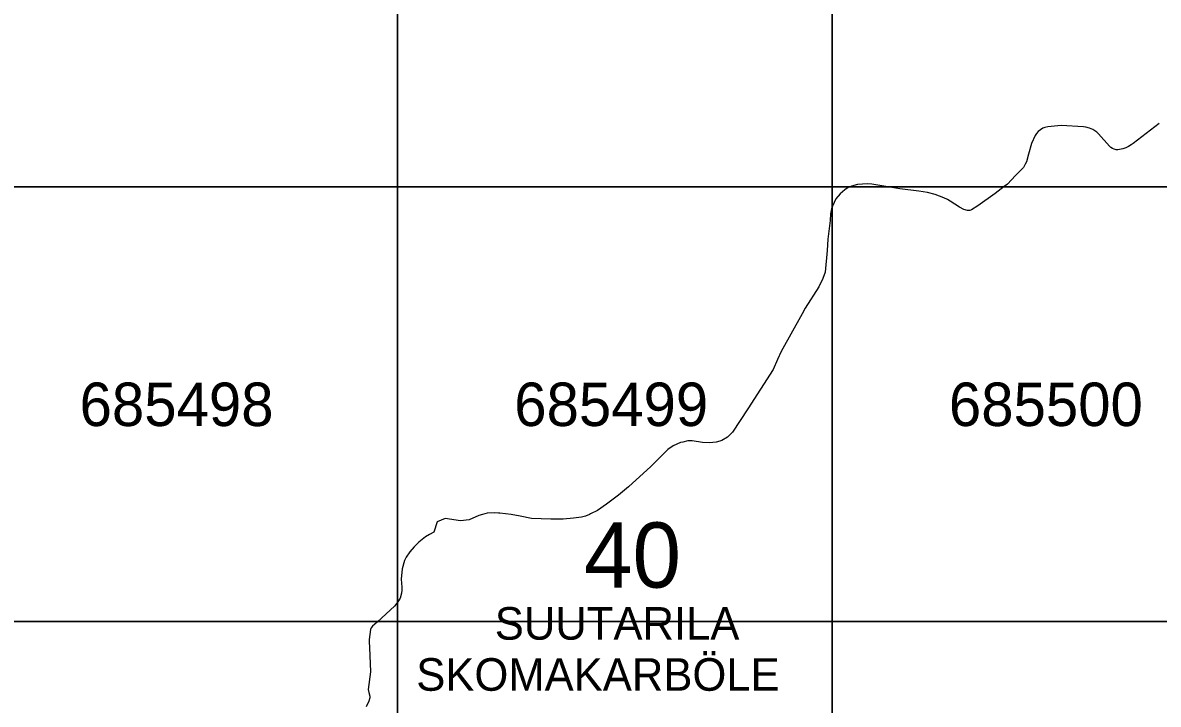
# Model space of a CAD drawing. Extents: x 25485000 to 25520000, y 6656775 to 6690000.
# Drawn here: x 25498138 to 25500750, y 6684810 to 6686378 of the extents above; entities that cross this region are included whole.
import ezdxf

# ---------------------------------------------------------------- set-up
doc = ezdxf.new("R2010")
doc.units = 0
doc.layers.add('Level 63', color=7, linetype='Continuous')

msp = doc.modelspace()

# ---------------------------------------------------------------- linework, layer by layer
at = {"layer": 'Level 63'}
for points in [[(25498000, 6686000), (25499000, 6686000), (25499000, 6687000), (25498000, 6687000)], [(25499000, 6686000), (25500000, 6686000), (25500000, 6687000), (25499000, 6687000)], [(25500000, 6686000), (25501000, 6686000), (25501000, 6687000), (25500000, 6687000)], [(25498000, 6685000), (25499000, 6685000), (25499000, 6686000), (25498000, 6686000)], [(25499000, 6685000), (25500000, 6685000), (25500000, 6686000), (25499000, 6686000)], [(25500000, 6685000), (25501000, 6685000), (25501000, 6686000), (25500000, 6686000)], [(25498000, 6684000), (25499000, 6684000), (25499000, 6685000), (25498000, 6685000)], [(25499000, 6684000), (25500000, 6684000), (25500000, 6685000), (25499000, 6685000)], [(25500000, 6684000), (25501000, 6684000), (25501000, 6685000), (25500000, 6685000)]]:
    msp.add_lwpolyline(points, close=True, dxfattribs=at)
msp.add_lwpolyline([(25500752.1, 6686146.3), (25500692.4, 6686100.4), (25500688.2, 6686097.3), (25500682, 6686093.5), (25500675.4, 6686090.4), (25500668.5, 6686087.9), (25500660.7, 6686086), (25500657.3, 6686085.6), (25500653, 6686085.7), (25500648.6, 6686086.8), (25500644.6, 6686088.5), (25500641.2, 6686090.8), (25500638.1, 6686093.9), (25500612.6, 6686122.2), (25500608.8, 6686125.8), (25500604.6, 6686128.9), (25500599.6, 6686132.1), (25500592.3, 6686135.2), (25500583.9, 6686137.5), (25500577.9, 6686138.2), (25500527.1, 6686141.2), (25500496, 6686138.1), (25500489.1, 6686136.7), (25500484.8, 6686135.1), (25500478.9, 6686131.8), (25500473.8, 6686127.7), (25500469.7, 6686123.2), (25500466.8, 6686118.7), (25500458.5, 6686100.2), (25500451.4, 6686075.3), (25500446.8, 6686057.5), (25500444, 6686052.4), (25500439.8, 6686044.6), (25500436.9, 6686041.6), (25500436.5, 6686041.2), (25500422, 6686026.2), (25500403, 6686006.6), (25500395.8, 6686001), (25500381.7, 6685990.1), (25500374.9, 6685984.8), (25500334.9, 6685956.6), (25500320.8, 6685947.5), (25500316.4, 6685946), (25500311.3, 6685945.8), (25500302.8, 6685948.3), (25500292.6, 6685953.9), (25500271.3, 6685967.5), (25500265.3, 6685971.2), (25500257, 6685975.4), (25500237.3, 6685982.6), (25500219.1, 6685987.1), (25500199.5, 6685990.5), (25500155.9, 6685996), (25500091.3, 6686006.3), (25500081.9, 6686007.1), (25500069.5, 6686006.7), (25500058.2, 6686005.4), (25500044.8, 6686002), (25500036.6, 6685998.5), (25500029.1, 6685993.5), (25500018.6, 6685984.3), (25500008.2, 6685972.8), (25500000.7, 6685956), (25499999.5, 6685953.3), (25499996.5, 6685938.2), (25499995.5, 6685923.2), (25499990.3, 6685880.1), (25499988.3, 6685853.6), (25499983.6, 6685804), (25499978.5, 6685789.1), (25499969.5, 6685770.4), (25499938.1, 6685721.3), (25499930.8, 6685708.1), (25499882.9, 6685621.4), (25499873.9, 6685603.4), (25499864.4, 6685579.9), (25499805.9, 6685489.8), (25499770.4, 6685435.6), (25499759, 6685424.7), (25499746.4, 6685416.4), (25499741.6, 6685415.3), (25499732.7, 6685413.1), (25499717.9, 6685411.3), (25499702, 6685412.4), (25499677.9, 6685416.3), (25499668.2, 6685416), (25499656.3, 6685413.2), (25499650.7, 6685411.8), (25499634.5, 6685404.2), (25499622, 6685395.8), (25499583, 6685356.8), (25499531.5, 6685310.4), (25499508, 6685291.1), (25499480.8, 6685270.2), (25499460.2, 6685256), (25499444.1, 6685247.7), (25499441.9, 6685246.6), (25499432.5, 6685242.9), (25499423, 6685240.5), (25499405.2, 6685238.1), (25499381, 6685236), (25499352.6, 6685235.6), (25499308, 6685237), (25499282.1, 6685242.8), (25499261.4, 6685246.3), (25499235.5, 6685249.6), (25499232.3, 6685249.9), (25499222.6, 6685250.5), (25499206.2, 6685249.7), (25499195.2, 6685246.6), (25499186.9, 6685244.3), (25499164.9, 6685234.3), (25499145.2, 6685232.2), (25499109.5, 6685237.4), (25499091, 6685230), (25499083.2, 6685205.8), (25499073.3, 6685200.5), (25499064.7, 6685195), (25499049.2, 6685182.5), (25499037.9, 6685172.4), (25499028, 6685160.7), (25499020.1, 6685148.4), (25499016.4, 6685140.4), (25499011, 6685121.7), (25499008, 6685097.9), (25499009.9, 6685079.4), (25499010.1, 6685072.1), (25499009.4, 6685065.7), (25499006.2, 6685054.4), (25499000.8, 6685045.8), (25498993.2, 6685035.9), (25498974.2, 6685017.7), (25498953.2, 6684999.2), (25498942.4, 6684989.3), (25498939.6, 6684986), (25498937.9, 6684981.8), (25498934.6, 6684959), (25498934.6, 6684953.3), (25498935.8, 6684940.4), (25498937.9, 6684884.3), (25498932.6, 6684844.1), (25498934, 6684837.3), (25498936.2, 6684828.4), (25498936.2, 6684824.4), (25498934.3, 6684817.3), (25498927.8, 6684803.7)], dxfattribs=at)

# ---------------------------------------------------------------- texts
for s, height, p in [('685498', 100, (25498268.5, 6685450)), ('685499', 100, (25499268.5, 6685450)), ('685500', 100, (25500268.5, 6685450)), ('40', 150, (25499429.1, 6685078.3)), ('SUUTARILA', 75, (25499223.7, 6684958.5)), ('SKOMAKARBÖLE', 75, (25499043.1, 6684841))]:
    msp.add_text(s, height=height, dxfattribs=at).set_placement(p)

doc.saveas('drawing.dxf')
